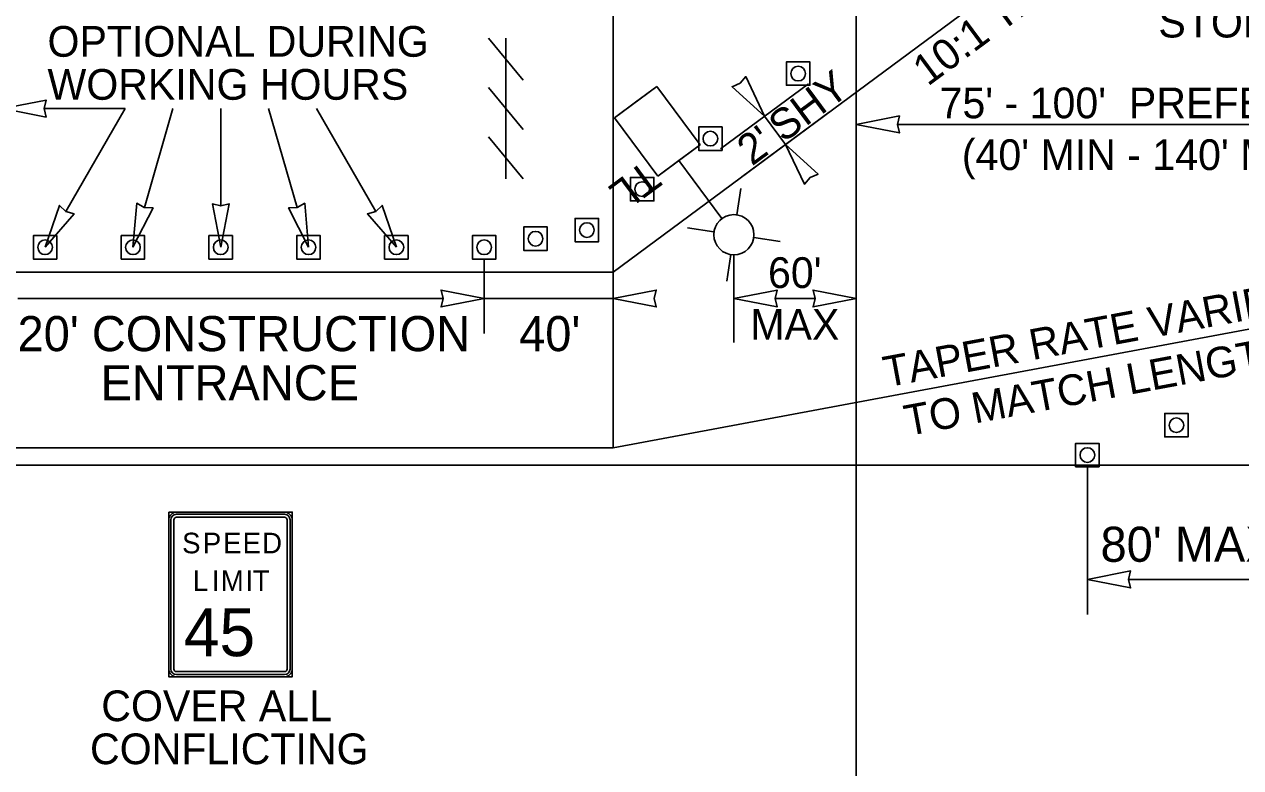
# Model space of a CAD drawing. Extents: x 99977 to 100176, y 99905 to 100011.
# Drawn here: x 100062.228 to 100064.999, y 99975.49 to 99977.184 of the extents above; entities that cross this region are included whole.
import ezdxf

# ---------------------------------------------------------------- set-up
doc = ezdxf.new("R2010")
doc.units = 0
for name, color, linetype in [('RD_ED_ShoulderPavedEdge', 7, 'Continuous'), ('RD_MK_LineEdgeWhite', 7, 'Continuous'), ('TR_SN_ConstructionSigns', 7, 'Continuous'), ('TR_WZ_BarricadeType3', 7, 'Continuous'), ('TR_WZ_PortableLightStandard', 7, 'Continuous'), ('TR_WZ_TrafficCone', 7, 'Continuous'), ('TR_WZ_WorkZoneDetails', 7, 'Continuous'), ('TR_WZ_WorkZoneTextCurrent', 7, 'Continuous')]:
    doc.layers.add(name, color=color, linetype=linetype)

msp = doc.modelspace()

# ---------------------------------------------------------------- linework, layer by layer
at = {"layer": 'RD_ED_ShoulderPavedEdge'}
msp.add_line((100060.3, 99976.1793), (100075.6425, 99976.1793), dxfattribs=at)
at = {"layer": 'RD_MK_LineEdgeWhite'}
for p, q in [((100064.8112, 99977.5393), (100063.5692, 99976.6193)), ((100063.5692, 99976.6193), (100060.3, 99976.6193)), ((100065.5008, 99976.5793), (100063.5692, 99976.2193)), ((100063.5692, 99976.2193), (100060.3, 99976.2193))]:
    msp.add_line(p, q, dxfattribs=at)
at = {"layer": 'TR_SN_ConstructionSigns'}
for p, q in [((100062.5571, 99975.715), (100062.5571, 99976.0549)), ((100062.5571, 99976.0549), (100062.5571, 99975.715)), ((100062.562, 99976.0549), (100062.562, 99975.715)), ((100062.5689, 99975.715), (100062.5689, 99976.0549)), ((100062.5747, 99976.0725), (100062.8208, 99976.0725)), ((100062.8208, 99976.0725), (100062.5747, 99976.0725)), ((100062.8208, 99976.0676), (100062.5747, 99976.0676)), ((100062.5747, 99976.0607), (100062.8208, 99976.0607)), ((100062.8267, 99976.0549), (100062.8267, 99975.715)), ((100062.8335, 99975.715), (100062.8335, 99976.0549)), ((100062.8384, 99976.0549), (100062.8384, 99975.715)), ((100062.8384, 99975.715), (100062.8384, 99976.0549)), ((100062.8208, 99975.7092), (100062.5747, 99975.7092)), ((100062.5747, 99975.7024), (100062.8208, 99975.7024)), ((100062.8208, 99975.6975), (100062.5747, 99975.6975)), ((100062.5747, 99975.6975), (100062.8208, 99975.6975))]:
    msp.add_line(p, q, dxfattribs=at)
msp.add_lwpolyline([(100062.5571, 99976.0725), (100062.8384, 99976.0725), (100062.8384, 99975.6975), (100062.5571, 99975.6975)], close=True, dxfattribs=at)
for centre, radius, start, end in [((100062.5747, 99976.0549), 0.0176, 90, 180), ((100062.5747, 99976.0549), 0.0176, 90, 180), ((100062.5747, 99976.0549), 0.0127, 90, 180), ((100062.5747, 99976.0549), 0.00586, 90, 180), ((100062.8208, 99976.0549), 0.0176, 0, 90), ((100062.8208, 99976.0549), 0.0176, 0, 90), ((100062.8208, 99976.0549), 0.0127, 0, 90), ((100062.8208, 99976.0549), 0.00586, 360, 90), ((100062.5747, 99975.715), 0.0176, 180, 270), ((100062.5747, 99975.715), 0.0176, 180, 270), ((100062.5747, 99975.715), 0.0127, 180, 270), ((100062.5747, 99975.715), 0.00586, 180, 270), ((100062.8208, 99975.715), 0.0176, 270, 0), ((100062.8208, 99975.715), 0.0127, 270, 360), ((100062.8208, 99975.715), 0.00586, 270, 0), ((100062.8208, 99975.715), 0.0176, 270, 0)]:
    msp.add_arc(centre, radius, start, end, dxfattribs=at)
at = {"layer": 'TR_WZ_BarricadeType3'}
for p, q in [((100063.3645, 99977.0567), (100063.2852, 99977.1522)), ((100063.3248, 99977.1522), (100063.3248, 99976.8322)), ((100063.3645, 99976.9445), (100063.2852, 99977.04)), ((100063.3645, 99976.8322), (100063.2852, 99976.9278))]:
    msp.add_line(p, q, dxfattribs=at)
at = {"layer": 'TR_WZ_PortableLightStandard'}
for p, q in [((100063.5722, 99976.9712), (100063.6686, 99977.0426)), ((100063.6686, 99977.0426), (100063.7674, 99976.9093)), ((100063.7674, 99976.9093), (100063.6686, 99977.0426)), ((100063.5722, 99976.9712), (100063.671, 99976.8379)), ((100063.5722, 99976.9712), (100063.671, 99976.8379)), ((100063.671, 99976.8379), (100063.7674, 99976.9093)), ((100063.7192, 99976.8736), (100063.817, 99976.7415)), ((100063.8511, 99976.75), (100063.8601, 99976.8102)), ((100063.799, 99976.7114), (100063.7389, 99976.7204)), ((100063.8896, 99976.698), (100063.9498, 99976.689)), ((100063.8375, 99976.6594), (100063.8286, 99976.5992))]:
    msp.add_line(p, q, dxfattribs=at)
for points in [[(100063.6686, 99977.0426), (100063.6204, 99977.0069), (100063.5722, 99976.9712)], [(100063.671, 99976.8379), (100063.7192, 99976.8736), (100063.7674, 99976.9093)]]:
    msp.add_lwpolyline(points, dxfattribs=at)
msp.add_circle((100063.8443, 99976.7047), 0.0457, dxfattribs=at)
msp.add_circle((100063.8443, 99976.7047), 0.0457, dxfattribs=at)
at = {"layer": 'TR_WZ_TrafficCone'}
for points in [[(100064.0174, 99977.0451), (100063.9641, 99977.0451), (100063.9641, 99977.0984), (100064.0174, 99977.0984), (100064.0174, 99977.0451)], [(100064.0174, 99977.0984), (100063.9641, 99977.0984), (100063.9641, 99977.0451), (100064.0174, 99977.0451), (100064.0174, 99977.0984)], [(100063.8174, 99976.8969), (100063.7641, 99976.8969), (100063.7641, 99976.9503), (100063.8174, 99976.9503), (100063.8174, 99976.8969)], [(100063.8174, 99976.9503), (100063.7641, 99976.9503), (100063.7641, 99976.8969), (100063.8174, 99976.8969), (100063.8174, 99976.9503)], [(100063.662, 99976.7818), (100063.6087, 99976.7818), (100063.6087, 99976.8352), (100063.662, 99976.8352), (100063.662, 99976.7818)], [(100063.662, 99976.8352), (100063.6087, 99976.8352), (100063.6087, 99976.7818), (100063.662, 99976.7818), (100063.662, 99976.8352)], [(100063.4192, 99976.669), (100063.3658, 99976.669), (100063.3658, 99976.7223), (100063.4192, 99976.7223), (100063.4192, 99976.669)], [(100063.4192, 99976.7223), (100063.3658, 99976.7223), (100063.3658, 99976.669), (100063.4192, 99976.669), (100063.4192, 99976.7223)], [(100063.4828, 99976.7419), (100063.5362, 99976.7419), (100063.5362, 99976.6886), (100063.4828, 99976.6886), (100063.4828, 99976.7419)], [(100063.4828, 99976.6886), (100063.5362, 99976.6886), (100063.5362, 99976.7419), (100063.4828, 99976.7419), (100063.4828, 99976.6886)], [(100062.3022, 99976.7026), (100062.2488, 99976.7026), (100062.2488, 99976.6493), (100062.3022, 99976.6493), (100062.3022, 99976.7026)], [(100062.3022, 99976.6493), (100062.2488, 99976.6493), (100062.2488, 99976.7026), (100062.3022, 99976.7026), (100062.3022, 99976.6493)], [(100062.5022, 99976.7026), (100062.4488, 99976.7026), (100062.4488, 99976.6493), (100062.5022, 99976.6493), (100062.5022, 99976.7026)], [(100062.5022, 99976.6493), (100062.4488, 99976.6493), (100062.4488, 99976.7026), (100062.5022, 99976.7026), (100062.5022, 99976.6493)], [(100062.7022, 99976.7026), (100062.6488, 99976.7026), (100062.6488, 99976.6493), (100062.7022, 99976.6493), (100062.7022, 99976.7026)], [(100062.7022, 99976.6493), (100062.6488, 99976.6493), (100062.6488, 99976.7026), (100062.7022, 99976.7026), (100062.7022, 99976.6493)], [(100062.9022, 99976.7026), (100062.8488, 99976.7026), (100062.8488, 99976.6493), (100062.9022, 99976.6493), (100062.9022, 99976.7026)], [(100062.9022, 99976.6493), (100062.8488, 99976.6493), (100062.8488, 99976.7026), (100062.9022, 99976.7026), (100062.9022, 99976.6493)], [(100063.1022, 99976.7026), (100063.0488, 99976.7026), (100063.0488, 99976.6493), (100063.1022, 99976.6493), (100063.1022, 99976.7026)], [(100063.1022, 99976.6493), (100063.0488, 99976.6493), (100063.0488, 99976.7026), (100063.1022, 99976.7026), (100063.1022, 99976.6493)], [(100063.3022, 99976.6493), (100063.2488, 99976.6493), (100063.2488, 99976.7026), (100063.3022, 99976.7026), (100063.3022, 99976.6493)], [(100063.3022, 99976.7026), (100063.2488, 99976.7026), (100063.2488, 99976.6493), (100063.3022, 99976.6493), (100063.3022, 99976.7026)], [(100064.8789, 99976.2439), (100064.8256, 99976.2439), (100064.8256, 99976.2973), (100064.8789, 99976.2973), (100064.8789, 99976.2439)], [(100064.8789, 99976.2973), (100064.8256, 99976.2973), (100064.8256, 99976.2439), (100064.8789, 99976.2439), (100064.8789, 99976.2973)], [(100064.6761, 99976.176), (100064.6227, 99976.176), (100064.6227, 99976.2293), (100064.6761, 99976.2293), (100064.6761, 99976.176)], [(100064.6761, 99976.2293), (100064.6227, 99976.2293), (100064.6227, 99976.176), (100064.6761, 99976.176), (100064.6761, 99976.2293)]]:
    msp.add_lwpolyline(points, dxfattribs=at)
for centre in [(100063.9907, 99977.0718), (100063.7907, 99976.9236), (100063.6354, 99976.8085), (100063.5095, 99976.7153), (100062.2755, 99976.676), (100062.4755, 99976.676), (100062.6755, 99976.676), (100062.8755, 99976.676), (100063.0755, 99976.676), (100063.2755, 99976.676), (100063.3925, 99976.6956), (100064.8523, 99976.2706), (100064.6494, 99976.2026)]:
    msp.add_circle(centre, 0.0167, dxfattribs=at)
at = {"layer": 'TR_WZ_WorkZoneDetails'}
for p, q in [((100063.5692, 99976.2193), (100063.5692, 99978.2793)), ((100064.1231, 99974.9817), (100064.1231, 99977.2294)), ((100063.8141, 99976.9003), (100064.0141, 99977.0484)), ((100062.2733, 99976.9922), (100062.4578, 99976.9922)), ((100062.3225, 99976.7578), (100062.4578, 99976.9922)), ((100062.5016, 99976.7667), (100062.5667, 99976.9922)), ((100062.6756, 99976.7703), (100062.6756, 99976.9922)), ((100062.8496, 99976.7667), (100062.7845, 99976.9922)), ((100063.0287, 99976.7578), (100062.8933, 99976.9922)), ((100063.8621, 99976.8363), (100064.0617, 99976.9841)), ((100064.2168, 99976.956), (100065.4071, 99976.956)), ((100063.2756, 99976.6493), (100063.2756, 99976.4793)), ((100063.8443, 99976.659), (100063.8443, 99976.4593)), ((100062.2137, 99976.5593), (100063.1819, 99976.5593)), ((100063.2756, 99976.5593), (100063.5692, 99976.5593)), ((100064.0294, 99976.5593), (100063.9381, 99976.5593)), ((100064.6494, 99975.8393), (100064.6494, 99976.1793)), ((100064.7431, 99975.9193), (100065.4071, 99975.9193))]:
    msp.add_line(p, q, dxfattribs=at)
for points in [[(100063.9143, 99976.9745), (100063.8713, 99977.0649), (100063.8585, 99977.0498), (100063.8403, 99977.042)], [(100062.1796, 99976.9922), (100062.2779, 99977.0115), (100062.2733, 99976.9922), (100062.2778, 99976.9729)], [(100064.1231, 99976.956), (100064.2214, 99976.9367), (100064.2168, 99976.956), (100064.2214, 99976.9753)], [(100063.9619, 99976.9102), (100064.0359, 99976.8427), (100064.0177, 99976.8349), (100064.0049, 99976.8198)], [(100062.2756, 99976.6766), (100062.3414, 99976.7521), (100062.3224, 99976.7578), (100062.308, 99976.7714)], [(100062.4756, 99976.6766), (100062.5213, 99976.7657), (100062.5015, 99976.7667), (100062.4843, 99976.7764)], [(100062.6756, 99976.6766), (100062.6564, 99976.7749), (100062.6756, 99976.7703), (100062.6949, 99976.7749)], [(100062.8756, 99976.6766), (100062.8299, 99976.7657), (100062.8496, 99976.7667), (100062.8669, 99976.7764)], [(100063.0756, 99976.6766), (100063.0098, 99976.7521), (100063.0288, 99976.7578), (100063.0432, 99976.7714)], [(100063.2756, 99976.5593), (100063.1773, 99976.5786), (100063.1819, 99976.5593), (100063.1773, 99976.54)], [(100063.5692, 99976.5593), (100063.6675, 99976.5786), (100063.6629, 99976.5593), (100063.6675, 99976.54)], [(100063.8443, 99976.5593), (100063.9426, 99976.5786), (100063.9381, 99976.5593), (100063.9426, 99976.54)], [(100064.1231, 99976.5593), (100064.0248, 99976.5786), (100064.0294, 99976.5593), (100064.0248, 99976.54)], [(100064.6494, 99975.9193), (100064.7477, 99975.9), (100064.7431, 99975.9193), (100064.7477, 99975.9386)]]:
    msp.add_lwpolyline(points, close=True, dxfattribs=at)
msp.add_lwpolyline([(100063.9143, 99976.9745), (100063.9619, 99976.9102)], dxfattribs=at)

# ---------------------------------------------------------------- texts
at = {"layer": 'TR_SN_ConstructionSigns'}
for s, height, p in [('S', 0.0469, (100062.5876, 99975.9787)), ('P', 0.0469, (100062.6349, 99975.9787)), ('E', 0.0469, (100062.6809, 99975.9787)), ('E', 0.0469, (100062.7254, 99975.9787)), ('D', 0.0469, (100062.7699, 99975.9787)), ('L', 0.0469, (100062.612, 99975.8928)), ('I', 0.0469, (100062.6551, 99975.8928)), ('M', 0.0469, (100062.6757, 99975.8928)), ('I', 0.0469, (100062.732, 99975.8928)), ('T', 0.0469, (100062.7484, 99975.8928)), ('45', 0.10937, (100062.5912, 99975.7443)), ('COVER ALL', 0.07, (100062.4035, 99975.5962)), ('CONFLICTING', 0.07, (100062.3778, 99975.4982))]:
    msp.add_text(s, height=height, dxfattribs=at).set_placement(p)
at = {"layer": 'TR_WZ_PortableLightStandard'}
msp.add_text('TL', height=0.07, rotation=216.5289, dxfattribs=at).set_placement((100063.6425, 99976.8765))
at = {"layer": 'TR_WZ_WorkZoneTextCurrent'}
for s, rotation, p in [('10:1 TAPER', 36.5289, (100064.2858, 99977.0415)), ('SHY', 36.5289, (100063.9571, 99976.9129)), ("2' ", 36.5289, (100063.8854, 99976.8598)), ("60'", 360, (100063.922, 99976.5833)), ('TAPER RATE VARIES', 10.5573, (100064.1918, 99976.3568)), ('MAX', 360, (100063.8817, 99976.4653)), ('TO MATCH LENGTH', 10.5573, (100064.2395, 99976.2457))]:
    msp.add_text(s, height=0.07, rotation=rotation, dxfattribs=at).set_placement(p)
for s, height, p in [('STOP BAR', 0.07, (100064.8112, 99977.1541)), ('OPTIONAL DURING', 0.07, (100062.281, 99977.1102)), ('WORKING HOURS', 0.07, (100062.281, 99977.0122)), ("75' - 100'  PREFERRED", 0.07, (100064.3128, 99976.97)), ("(40' MIN - 140' MAX)", 0.07, (100064.3635, 99976.852)), ("120' CONSTRUCTION", 0.08, (100062.1533, 99976.4393)), ("40'", 0.08, (100063.3552, 99976.4393)), ('ENTRANCE', 0.08, (100062.402, 99976.3273)), ("80' MAX", 0.08, (100064.6794, 99975.9593))]:
    msp.add_text(s, height=height, dxfattribs=at).set_placement(p)

doc.saveas('drawing.dxf')
